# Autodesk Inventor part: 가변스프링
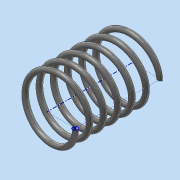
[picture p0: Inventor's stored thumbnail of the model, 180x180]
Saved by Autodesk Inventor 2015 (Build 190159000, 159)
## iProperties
Created: 2016-06
Part Number: 가변스프링
Material: 스테인레스 스틸
Document SubType Name: Modeling
Designer: nami
Density: 8 g/cm^3
Appearance: 반연마
Mass: 84.223 g
Surface Area: 106.459 cm^2
Volume: 10.5279 cm^3
Author: nami
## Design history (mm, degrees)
sketch "스케치1"
  geometry: L1 (0, 0)-(22.5, 0); L2 (22.5, 0)-(22.5, 67.25); L3 (22.5, 67.25)-(0, 67.25); L4 (0, 67.25)-(0, 0); C1 r 2 at (22.5, 0)
  constraints: 8 end point, 2 parallel, 1 centre point, 1 coincident, 1 horizontal, 1 perpendicular
  dimensions: "d0" = 45 diameter of L2 L4; "d1" = 4 diameter of C1; "d2" = 67.25 distance of L3.end L1.start (derived)
feature "코일1" sketch "스케치1" pitch "d3" = 10; turns "d5" = 6; dims "d4" = 67.25 (= d2), "d6" = 0, angle "d7" = 90 deg, angle "d8" = 90 deg, "d9" = 0, "d10" = 0
sketch "스케치2"
  geometry: L1 (-24.5, 0)-(-20.5, 0) reference; 1 further point
  constraints: 1 horizontal alignment
extrude "돌출1" cut sketch "스케치2" distance "d11" = 10; taper "d12" = 0 deg
node "작업 평면1"
sketch "스케치3"
  geometry: L1 (2, 0)-(-2, 0) reference; 1 further point
  constraints: 1 horizontal alignment
extrude "돌출2" cut sketch "스케치3" distance "d14" = 10; taper "d15" = 0 deg
node "솔리드1"
node "절단 모서리 투영1"
node "절단 모서리 투영2"
other parameters: "d13" = 0
